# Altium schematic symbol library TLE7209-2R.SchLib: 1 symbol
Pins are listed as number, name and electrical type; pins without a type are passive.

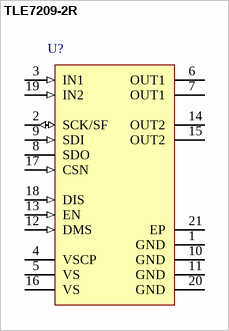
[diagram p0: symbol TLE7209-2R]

## TLE7209-2R
designator U?
7 A H-Bridge for DC-Motor Applications, 5 to 28 V, 150 mOhm RDS(on), PG-DSO-20-37, Reel, Green; Manufacturer: Infineon; PartNumber: TLE7209-2R; Current Limit (min.): 5.5 A; Green: TRUE; Operating Range: 5 to 28 V; Quiescent Current (max.): 20 mA; RthJC (max): 1.5 K/W
footprint INF-PG-DSO-20-37_N (SOP, 20-Leads, Body 15.9x11mm, Pitch 1.27mm, Thermal Pad 15.84x6mm, IPC Medium Density)
footprint INF-PG-DSO-20-37_L (SOP, 20-Leads, Body 15.9x11mm, Pitch 1.27mm, Thermal Pad 15.84x6mm, IPC High Density)
footprint INF-PG-DSO-20-37_M (SOP, 20-Leads, Body 15.9x11mm, Pitch 1.27mm, Thermal Pad 15.84x6mm, IPC Low Density)
pins: 1 GND (power) "Ground", 2 SCK/SF (io) "SPI-Clock/Status-flag", 3 IN1 (in) "Input 1", 4 VSCP (power) "Supply voltage for internal charge pump", 5 VS (power) "Supply voltage; connect pins externally", 6 OUT1 (power) "Output 1; connect pins externally", 7 OUT1 (power) "Output 1; connect pins externally", 8 SDO (hiz) "Serial data out", 9 SDI (in) "Serial data in", 10 GND (power) "Ground", 11 GND (power) "Ground", 12 DMS (in) "Diagnostic-Mode selection (+ Supply voltage for SPI-Interface)", 13 EN (in) "Enable", 14 OUT2 (power) "Output 2; connect pins externally", 15 OUT2 (power) "Output 2; connect pins externally", 16 VS (power) "Supply voltage; connect pins externally", 17 CSN (in) "Chip Select (low active)", 18 DIS (in) "Disable", 19 IN2 (in) "Input 2", 20 GND (power) "Ground", 21 EP (power)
